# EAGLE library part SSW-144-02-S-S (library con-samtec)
THROUGH-HOLE .025" SQ POST SOCKET Source: Samtec SSW.pdf
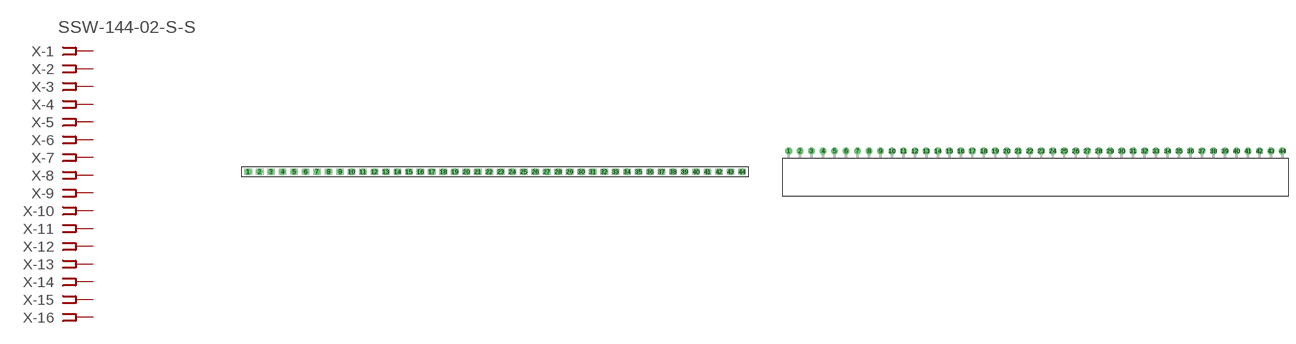
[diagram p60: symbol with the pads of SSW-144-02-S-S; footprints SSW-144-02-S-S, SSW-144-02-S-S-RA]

Designator prefix X; gates -1=FPINV -2=FPIN -3=FPIN -4=FPIN -5=FPIN -6=FPIN -7=FPIN -8=FPIN -9=FPIN -10=FPIN -11=FPIN -12=FPIN -13=FPIN -14=FPIN -15=FPIN -16=FPIN -17=FPIN -18=FPIN -19=FPIN -20=FPIN -21=FPIN -22=FPIN -23=FPIN -24=FPIN -25=FPIN -26=FPIN -27=FPIN -28=FPIN -29=FPIN -30=FPIN -31=FPIN -32=FPIN -33=FPIN -34=FPIN -35=FPIN -36=FPIN -37=FPIN -38=FPIN -39=FPIN -40=FPIN -41=FPIN -42=FPIN -43=FPIN -44=FPIN

## SSW-144-02-S-S (OC_FARNELL: unknown; OC_NEWARK: unknown)  [SSW-144-02-S-S]
1  -1:1  pas
2  -2:1  pas
3  -3:1  pas
4  -4:1  pas
5  -5:1  pas
6  -6:1  pas
7  -7:1  pas
8  -8:1  pas
9  -9:1  pas
10  -10:1  pas
11  -11:1  pas
12  -12:1  pas
13  -13:1  pas
14  -14:1  pas
15  -15:1  pas
16  -16:1  pas
17  -17:1  pas
18  -18:1  pas
19  -19:1  pas
20  -20:1  pas
21  -21:1  pas
22  -22:1  pas
23  -23:1  pas
24  -24:1  pas
25  -25:1  pas
26  -26:1  pas
27  -27:1  pas
28  -28:1  pas
29  -29:1  pas
30  -30:1  pas
31  -31:1  pas
32  -32:1  pas
33  -33:1  pas
34  -34:1  pas
35  -35:1  pas
36  -36:1  pas
37  -37:1  pas
38  -38:1  pas
39  -39:1  pas
40  -40:1  pas
41  -41:1  pas
42  -42:1  pas
43  -43:1  pas
44  -44:1  pas

## SSW-144-02-S-S-RA (OC_FARNELL: unknown; OC_NEWARK: unknown)  [SSW-144-02-S-S-RA]
Pads as for SSW-144-02-S-S

## Footprint SSW-144-02-S-S (pad centres in mm)
THROUGH-HOLE .025" SQ POST SOCKET Source: Samtec SSW.pdf
drill 1 pad 1.5 octagon: 1 -54.61,0; 2 -52.07,0; 3 -49.53,0; 4 -46.99,0; 5 -44.45,0; 6 -41.91,0; 7 -39.37,0; 8 -36.83,0; 9 -34.29,0; 10 -31.75,0; 11 -29.21,0; 12 -26.67,0; 13 -24.13,0; 14 -21.59,0; 15 -19.05,0; 16 -16.51,0; 17 -13.97,0; 18 -11.43,0; 19 -8.89,0; 20 -6.35,0; 21 -3.81,0; 22 -1.27,0; 23 1.27,0; 24 3.81,0; 25 6.35,0; 26 8.89,0; 27 11.43,0; 28 13.97,0; 29 16.51,0; 30 19.05,0; 31 21.59,0; 32 24.13,0; 33 26.67,0; 34 29.21,0; 35 31.75,0; 36 34.29,0; 37 36.83,0; 38 39.37,0; 39 41.91,0; 40 44.45,0; 41 46.99,0; 42 49.53,0; 43 52.07,0; 44 54.61,0

## Footprint SSW-144-02-S-S-RA (pad centres in mm)
THROUGH-HOLE .025" SQ POST SOCKET Source: Samtec SSW.pdf
drill 1 pad 1.5 octagon: 1 -54.61,1.524; 2 -52.07,1.524; 3 -49.53,1.524; 4 -46.99,1.524; 5 -44.45,1.524; 6 -41.91,1.524; 7 -39.37,1.524; 8 -36.83,1.524; 9 -34.29,1.524; 10 -31.75,1.524; 11 -29.21,1.524; 12 -26.67,1.524; 13 -24.13,1.524; 14 -21.59,1.524; 15 -19.05,1.524; 16 -16.51,1.524; 17 -13.97,1.524; 18 -11.43,1.524; 19 -8.89,1.524; 20 -6.35,1.524; 21 -3.81,1.524; 22 -1.27,1.524; 23 1.27,1.524; 24 3.81,1.524; 25 6.35,1.524; 26 8.89,1.524; 27 11.43,1.524; 28 13.97,1.524; 29 16.51,1.524; 30 19.05,1.524; 31 21.59,1.524; 32 24.13,1.524; 33 26.67,1.524; 34 29.21,1.524; 35 31.75,1.524; 36 34.29,1.524; 37 36.83,1.524; 38 39.37,1.524; 39 41.91,1.524; 40 44.45,1.524; 41 46.99,1.524; 42 49.53,1.524; 43 52.07,1.524; 44 54.61,1.524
